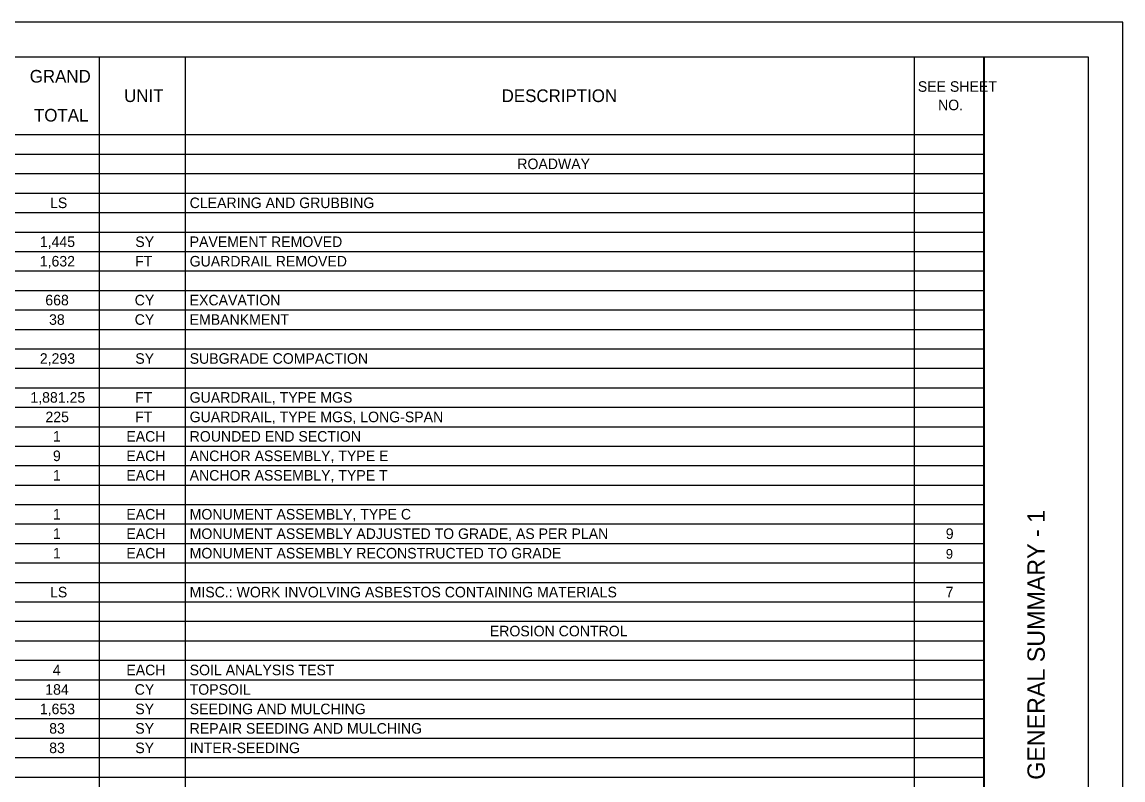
# Model space of a CAD drawing. Extents: x -31.7 to 37.3, y 0 to 22.
# Drawn here: x 18.16 to 34, y 11.1 to 22 of the extents above; entities that cross this region are included whole.
import ezdxf

# ---------------------------------------------------------------- set-up
doc = ezdxf.new("R2010")
doc.units = 0
for name, color, linetype in [('SH_Border', 7, 'Continuous'), ('SH_Cut_Line', 7, 'Continuous'), ('SH_Data', 7, 'Continuous'), ('SH_Text', 7, 'Continuous')]:
    doc.layers.add(name, color=color, linetype=linetype)

msp = doc.modelspace()

# ---------------------------------------------------------------- linework, layer by layer
at = {"layer": 'SH_Border'}
msp.add_line((32, 0.5), (32, 21.5), dxfattribs=at)
msp.add_lwpolyline([(1.5, 21.5), (33.5, 21.5), (33.5, 0.5), (1.5, 0.5)], close=True, dxfattribs=at)
at = {"layer": 'SH_Cut_Line'}
msp.add_lwpolyline([(0, 0), (34, 0), (34, 22), (0, 22)], close=True, dxfattribs=at)
at = {"layer": 'SH_Data'}
for p, q in [((1.5, 21.5), (32.001, 21.5)), ((19.27, 21.5), (19.27, 0.502)), ((20.506, 21.5), (20.506, 0.502)), ((30.997, 21.5), (30.997, 0.502)), ((32.001, 21.5), (32.001, 0.502)), ((1.5, 20.38), (32.001, 20.38)), ((1.5, 20.1), (32.001, 20.1)), ((1.5, 19.82), (32.001, 19.82)), ((1.5, 19.54), (32.001, 19.54)), ((1.5, 19.26), (32.001, 19.26)), ((1.5, 18.98), (32.001, 18.98)), ((1.5, 18.7), (32.001, 18.7)), ((1.5, 18.42), (32.001, 18.42)), ((1.5, 18.14), (32.001, 18.14)), ((1.5, 17.86), (32.001, 17.86)), ((1.5, 17.58), (32.001, 17.58)), ((1.5, 17.3), (32.001, 17.3)), ((1.5, 17.02), (32.001, 17.02)), ((1.5, 16.74), (32.001, 16.74)), ((1.5, 16.46), (32.001, 16.46)), ((1.5, 16.18), (32.001, 16.18)), ((1.5, 15.9), (32.001, 15.9)), ((1.5, 15.62), (32.001, 15.62)), ((1.5, 15.34), (32.001, 15.34)), ((1.5, 15.061), (32.001, 15.061)), ((1.5, 14.781), (32.001, 14.781)), ((1.5, 14.501), (32.001, 14.501)), ((1.5, 14.221), (32.001, 14.221)), ((1.5, 13.941), (32.001, 13.941)), ((1.5, 13.661), (32.001, 13.661)), ((1.5, 13.381), (32.001, 13.381)), ((1.5, 13.101), (32.001, 13.101)), ((1.5, 12.821), (32.001, 12.821)), ((1.5, 12.541), (32.001, 12.541)), ((1.5, 12.261), (32.001, 12.261)), ((1.5, 11.981), (32.001, 11.981)), ((1.5, 11.701), (32.001, 11.701)), ((1.5, 11.421), (32.001, 11.421)), ((1.5, 11.141), (32.001, 11.141))]:
    msp.add_line(p, q, dxfattribs=at)

# ---------------------------------------------------------------- texts
msp.add_text('GENERAL SUMMARY - 1', height=0.25, rotation=90, dxfattribs=at).set_placement((32.875, 11.102))
msp.add_text('9', height=0.14, dxfattribs=at).set_placement((31.451, 14.281))
at = {"layer": 'SH_Text'}
for s, height, p in [('GRAND', 0.1818, (18.27, 21.129)), ('SEE SHEET ', 0.1515, (31.048, 20.997)), ('UNIT', 0.1818, (19.628, 20.849)), ('DESCRIPTION', 0.18182, (25.06, 20.849)), ('TOTAL', 0.1818, (18.331, 20.569)), ('NO.', 0.1515, (31.339, 20.732)), ('ROADWAY', 0.1515, (25.285, 19.884)), ('LS', 0.1515, (18.562, 19.324)), ('CLEARING AND GRUBBING', 0.15152, (20.571, 19.324)), ('1,445', 0.1515, (18.415, 18.764)), ('SY', 0.1515, (19.789, 18.764)), ('PAVEMENT REMOVED', 0.15152, (20.571, 18.764)), ('1,632', 0.1515, (18.414, 18.484)), ('FT', 0.1515, (19.787, 18.484)), ('GUARDRAIL REMOVED', 0.15152, (20.571, 18.484)), ('668', 0.1515, (18.494, 17.925)), ('CY', 0.1515, (19.78, 17.925)), ('EXCAVATION', 0.1515, (20.571, 17.925)), ('38', 0.1515, (18.548, 17.645)), ('CY', 0.1515, (19.78, 17.645)), ('EMBANKMENT', 0.1515, (20.571, 17.645)), ('2,293', 0.1515, (18.415, 17.085)), ('SY', 0.1515, (19.789, 17.085)), ('SUBGRADE COMPACTION', 0.15152, (20.571, 17.085)), ('1,881.25', 0.1515, (18.279, 16.525)), ('FT', 0.1515, (19.787, 16.525)), ('GUARDRAIL, TYPE MGS', 0.15152, (20.571, 16.525)), ('225', 0.1515, (18.496, 16.245)), ('FT', 0.1515, (19.787, 16.245)), ('GUARDRAIL, TYPE MGS, LONG-SPAN', 0.15152, (20.571, 16.245)), ('1', 0.152, (18.604, 15.965)), ('EACH', 0.1515, (19.66, 15.965)), ('ROUNDED END SECTION', 0.15152, (20.571, 15.965)), ('9', 0.152, (18.604, 15.685)), ('EACH', 0.1515, (19.66, 15.685)), ('ANCHOR ASSEMBLY, TYPE E', 0.15152, (20.571, 15.685)), ('1', 0.152, (18.604, 15.405)), ('EACH', 0.1515, (19.66, 15.405)), ('ANCHOR ASSEMBLY, TYPE T', 0.15152, (20.571, 15.405)), ('1', 0.152, (18.604, 14.845)), ('EACH', 0.1515, (19.66, 14.845)), ('MONUMENT ASSEMBLY, TYPE C', 0.15152, (20.571, 14.845)), ('1', 0.152, (18.604, 14.565)), ('EACH', 0.1515, (19.66, 14.565)), ('MONUMENT ASSEMBLY ADJUSTED TO GRADE, AS PER PLAN', 0.15152, (20.571, 14.565)), ('9', 0.152, (31.45, 14.565)), ('1', 0.152, (18.604, 14.285)), ('EACH', 0.1515, (19.66, 14.285)), ('MONUMENT ASSEMBLY RECONSTRUCTED TO GRADE', 0.15152, (20.571, 14.285)), ('LS', 0.1515, (18.562, 13.725)), ('MISC.: WORK INVOLVING ASBESTOS CONTAINING MATERIALS', 0.15152, (20.571, 13.725)), ('7', 0.152, (31.449, 13.725)), ('EROSION CONTROL', 0.15152, (24.89, 13.165)), ('4', 0.152, (18.601, 12.605)), ('EACH', 0.1515, (19.66, 12.605)), ('SOIL ANALYSIS TEST', 0.15152, (20.571, 12.605)), ('184', 0.1515, (18.493, 12.325)), ('CY', 0.1515, (19.78, 12.325)), ('TOPSOIL', 0.1515, (20.571, 12.325)), ('1,653', 0.1515, (18.415, 12.045)), ('SY', 0.1515, (19.789, 12.045)), ('SEEDING AND MULCHING', 0.15152, (20.571, 12.045)), ('83', 0.1515, (18.55, 11.765)), ('SY', 0.1515, (19.789, 11.765)), ('REPAIR SEEDING AND MULCHING', 0.15152, (20.571, 11.765)), ('83', 0.1515, (18.55, 11.485)), ('SY', 0.1515, (19.789, 11.485)), ('INTER-SEEDING', 0.15152, (20.571, 11.485))]:
    msp.add_text(s, height=height, dxfattribs=at).set_placement(p)

doc.saveas('drawing.dxf')
